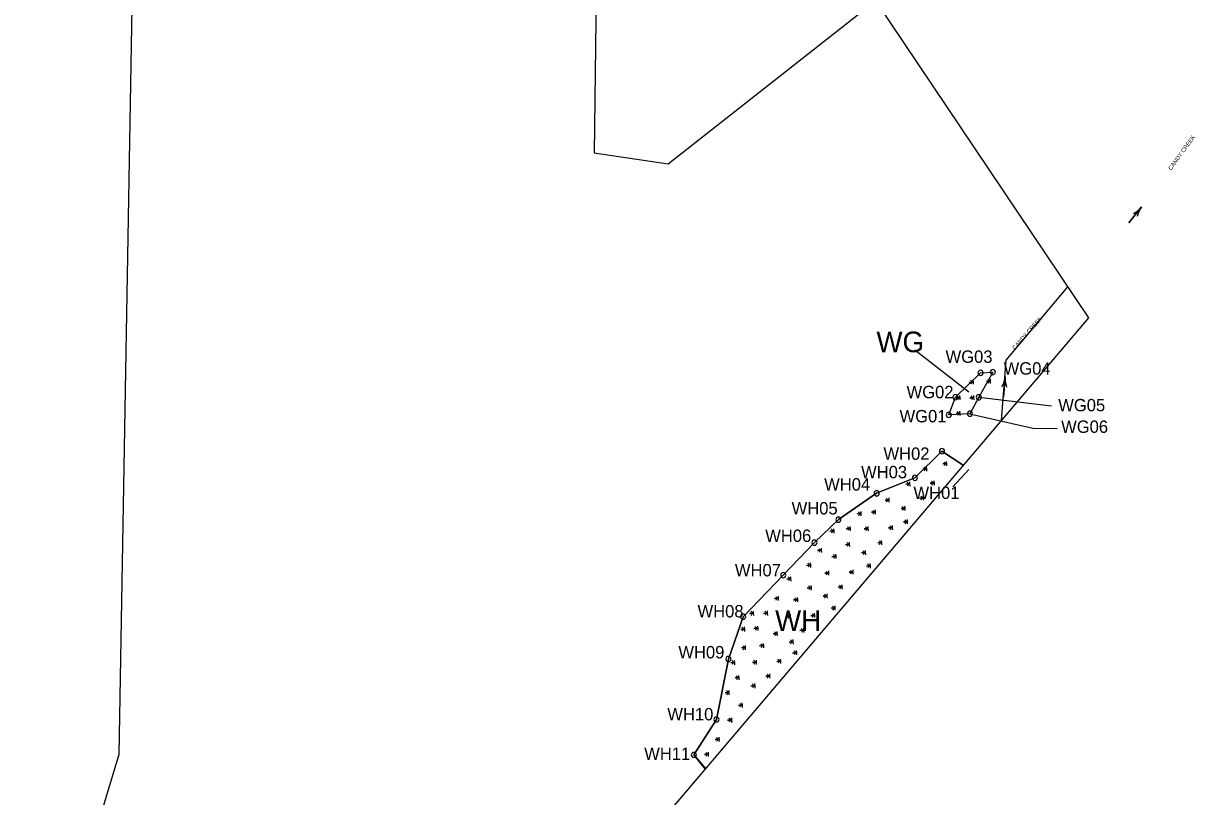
# Model space of a CAD drawing. Extents: x 1807340 to 1808565, y 913462 to 916154.
# Drawn here: x 1807430 to 1808565, y 914655 to 915405 of the extents above; entities that cross this region are included whole.
import ezdxf

# ---------------------------------------------------------------- set-up
doc = ezdxf.new("R2010")
doc.units = 0
for name, color, linetype in [('Default', 7, 'Continuous'), ('Exist Environmental Wetland Boundary', 7, 'Continuous'), ('Exist Hydro River Flow Arrow CELL', 7, 'Continuous'), ('Exist Hydro Stream or Body of Water Text', 7, 'Continuous'), ('Old_Level_60', 7, 'Continuous'), ('Old_Level_61', 7, 'Continuous'), ('Prop PHM Study Limits Alternate 1', 7, 'Continuous')]:
    doc.layers.add(name, color=color, linetype=linetype)

# ---------------------------------------------------------------- blocks, each defined once
blk = doc.blocks.new('WetlandPoint')
at = {"layer": 'Default'}
for start, end in [(0, 180), (180, 0)]:
    blk.add_arc((0, 0), 0.782, start, end, dxfattribs=at)

msp = doc.modelspace()

# ---------------------------------------------------------------- linework, layer by layer
at = {"layer": 'Default'}
msp.add_line((1808346.4, 914972.5), (1808331, 914955.6), dxfattribs=at)
msp.add_lwpolyline([(1808341.1, 914976.7), (1808320.4, 914990.3), (1808294.2, 914964.5), (1808257.1, 914949.4), (1808220, 914923.9), (1808196.8, 914901.6), (1808166.6, 914870), (1808127.7, 914829.8), (1808113.4, 914788.8), (1808101.8, 914730.1), (1808079.9, 914695.8), (1808091.1, 914682.5)], dxfattribs=at)
at = {"layer": 'Exist Environmental Wetland Boundary'}
msp.add_lwpolyline([(1808327, 915025.4), (1808333.4, 915042.7), (1808357.8, 915066.2), (1808369.7, 915066.9), (1808356.1, 915042.5), (1808347.5, 915026.6)], close=True, dxfattribs=at)
for points in [[(1808351, 915055.1), (1808350.9, 915057.2), (1808346.9, 915057), (1808350.9, 915057.2), (1808350.8, 915059.3)], [(1808367.5, 915055.9), (1808367.4, 915058), (1808363.5, 915057.8), (1808367.4, 915058), (1808367.3, 915060.2)], [(1808338, 915039.9), (1808337.9, 915042.1), (1808334, 915041.9), (1808337.9, 915042.1), (1808337.8, 915044.2)], [(1808351.5, 915039.9), (1808351.4, 915042.1), (1808347.5, 915041.9), (1808351.4, 915042.1), (1808351.3, 915044.2)], [(1808351.5, 915039.9), (1808351.4, 915042.1), (1808347.5, 915041.9), (1808351.4, 915042.1), (1808351.3, 915044.2)], [(1808338.1, 915024.7), (1808338, 915026.9), (1808334, 915026.7), (1808338, 915026.9), (1808337.8, 915029)], [(1808091, 914682.4), (1808079.9, 914695.8), (1808101.8, 914730.1), (1808113.4, 914788.8), (1808127.7, 914829.8), (1808166.6, 914870), (1808196.8, 914901.6), (1808196.8, 914901.6), (1808196.8, 914901.6), (1808196.8, 914901.6), (1808220, 914923.9), (1808257.1, 914949.4), (1808294.2, 914964.5), (1808320.4, 914990.3), (1808341.1, 914976.7)], [(1808325.2, 914976), (1808325.1, 914978.2), (1808321.1, 914977.9), (1808325.1, 914978.2), (1808324.9, 914980.3)], [(1808305.8, 914970.9), (1808305.7, 914973.1), (1808301.7, 914972.9), (1808305.7, 914973.1), (1808305.5, 914975.2)], [(1808289.5, 914956.3), (1808289.4, 914958.5), (1808285.5, 914958.2), (1808289.4, 914958.5), (1808289.3, 914960.6)], [(1808313.1, 914957.3), (1808313, 914959.4), (1808309, 914959.2), (1808313, 914959.4), (1808312.8, 914961.6)], [(1808269.3, 914940.7), (1808269.2, 914942.8), (1808265.2, 914942.6), (1808269.2, 914942.8), (1808269.1, 914945)], [(1808302.6, 914942.8), (1808302.5, 914945), (1808298.5, 914944.7), (1808302.5, 914945), (1808302.3, 914947.1)], [(1808242.2, 914927.5), (1808242.1, 914929.7), (1808238.2, 914929.5), (1808242.1, 914929.7), (1808242, 914931.8)], [(1808242.2, 914927.5), (1808242.1, 914929.7), (1808238.2, 914929.5), (1808242.1, 914929.7), (1808242, 914931.8)], [(1808256.1, 914929.1), (1808256, 914931.2), (1808252, 914931), (1808256, 914931.2), (1808255.9, 914933.4)], [(1808284.8, 914932.7), (1808284.7, 914934.8), (1808280.7, 914934.6), (1808284.7, 914934.8), (1808284.5, 914937)], [(1808287.1, 914919.8), (1808287, 914921.9), (1808283.1, 914921.7), (1808287, 914921.9), (1808286.9, 914924.1)], [(1808215.9, 914910.8), (1808215.8, 914912.9), (1808211.8, 914912.7), (1808215.8, 914912.9), (1808215.7, 914915.1)], [(1808231.7, 914913.1), (1808231.6, 914915.2), (1808227.7, 914915), (1808231.6, 914915.2), (1808231.5, 914917.3)], [(1808231.7, 914913.1), (1808231.6, 914915.2), (1808227.7, 914915), (1808231.6, 914915.2), (1808231.5, 914917.3)], [(1808249.1, 914913), (1808249, 914915.1), (1808245.1, 914914.9), (1808249, 914915.1), (1808248.9, 914917.3)], [(1808272.7, 914914), (1808272.6, 914916.1), (1808268.6, 914915.9), (1808272.6, 914916.1), (1808272.4, 914918.3)], [(1808231.1, 914897.7), (1808230.9, 914899.8), (1808227, 914899.6), (1808230.9, 914899.8), (1808230.8, 914902)], [(1808262.2, 914899.5), (1808262.1, 914901.6), (1808258.1, 914901.4), (1808262.1, 914901.6), (1808261.9, 914903.8)], [(1808203.8, 914892.1), (1808203.7, 914894.2), (1808199.7, 914894), (1808203.7, 914894.2), (1808203.6, 914896.3)], [(1808217.9, 914886.1), (1808217.7, 914888.2), (1808213.8, 914888), (1808217.7, 914888.2), (1808217.6, 914890.4)], [(1808246.5, 914889.7), (1808246.4, 914891.9), (1808242.5, 914891.6), (1808246.4, 914891.9), (1808246.3, 914894)], [(1808193.3, 914877.6), (1808193.2, 914879.7), (1808189.2, 914879.5), (1808193.2, 914879.7), (1808193.1, 914881.9)], [(1808210.9, 914870), (1808210.8, 914872.1), (1808206.8, 914871.9), (1808210.8, 914872.1), (1808210.6, 914874.3)], [(1808234.4, 914871), (1808234.3, 914873.1), (1808230.4, 914872.9), (1808234.3, 914873.1), (1808234.2, 914875.3)], [(1808251.1, 914877), (1808251, 914879.1), (1808247.1, 914878.9), (1808251, 914879.1), (1808250.9, 914881.3)], [(1808174.1, 914864.3), (1808174, 914866.4), (1808170.1, 914866.2), (1808174, 914866.4), (1808173.9, 914868.6)], [(1808193.9, 914855.6), (1808193.8, 914857.8), (1808189.8, 914857.6), (1808193.8, 914857.8), (1808193.7, 914859.9)], [(1808209.4, 914847.7), (1808209.2, 914849.8), (1808205.3, 914849.6), (1808209.2, 914849.8), (1808209.1, 914852)], [(1808223.9, 914856.5), (1808223.8, 914858.6), (1808219.9, 914858.4), (1808223.8, 914858.6), (1808223.7, 914860.8)], [(1808162, 914845.5), (1808161.9, 914847.7), (1808158, 914847.5), (1808161.9, 914847.7), (1808161.8, 914849.8)], [(1808180.7, 914844.1), (1808180.6, 914846.2), (1808176.6, 914846), (1808180.6, 914846.2), (1808180.5, 914848.3)], [(1808217, 914836.1), (1808216.9, 914838.3), (1808213, 914838.1), (1808216.9, 914838.3), (1808216.8, 914840.4)], [(1808137.9, 914831), (1808137.8, 914833.2), (1808133.9, 914832.9), (1808137.8, 914833.2), (1808137.7, 914835.3)], [(1808151.5, 914831.1), (1808151.4, 914833.2), (1808147.5, 914833), (1808151.4, 914833.2), (1808151.3, 914835.4)], [(1808173.7, 914827.9), (1808173.6, 914830.1), (1808169.6, 914829.9), (1808173.6, 914830.1), (1808173.5, 914832.2)], [(1808197.3, 914828.9), (1808197.1, 914831.1), (1808193.2, 914830.8), (1808197.1, 914831.1), (1808197, 914833.2)], [(1808129.4, 914815.6), (1808129.3, 914817.7), (1808125.3, 914817.5), (1808129.3, 914817.7), (1808129.1, 914819.9)], [(1808142.3, 914816.4), (1808142.1, 914818.6), (1808138.2, 914818.4), (1808142.1, 914818.6), (1808142, 914820.7)], [(1808186.8, 914814.5), (1808186.6, 914816.6), (1808182.7, 914816.4), (1808186.6, 914816.6), (1808186.5, 914818.7)], [(1808160.9, 914811.2), (1808160.8, 914813.4), (1808156.8, 914813.2), (1808160.8, 914813.4), (1808160.7, 914815.5)], [(1808160.9, 914811.2), (1808160.8, 914813.4), (1808156.8, 914813.2), (1808160.8, 914813.4), (1808160.7, 914815.5)], [(1808176.4, 914803.3), (1808176.3, 914805.4), (1808172.3, 914805.2), (1808176.3, 914805.4), (1808176.1, 914807.6)], [(1808176.4, 914803.3), (1808176.3, 914805.4), (1808172.3, 914805.2), (1808176.3, 914805.4), (1808176.1, 914807.6)], [(1808130.1, 914797.7), (1808130, 914799.9), (1808126.1, 914799.6), (1808130, 914799.9), (1808129.9, 914802)], [(1808147.7, 914799.7), (1808147.6, 914801.8), (1808143.6, 914801.6), (1808147.6, 914801.8), (1808147.5, 914803.9)], [(1808147.7, 914799.7), (1808147.6, 914801.8), (1808143.6, 914801.6), (1808147.6, 914801.8), (1808147.5, 914803.9)], [(1808179.7, 914792.7), (1808179.6, 914794.9), (1808175.6, 914794.6), (1808179.6, 914794.9), (1808179.4, 914797)], [(1808119.7, 914783.2), (1808119.5, 914785.4), (1808115.6, 914785.2), (1808119.5, 914785.4), (1808119.4, 914787.5)], [(1808140.7, 914783.5), (1808140.6, 914785.7), (1808136.6, 914785.5), (1808140.6, 914785.7), (1808140.5, 914787.8)], [(1808140.7, 914783.5), (1808140.6, 914785.7), (1808136.6, 914785.5), (1808140.6, 914785.7), (1808140.5, 914787.8)], [(1808164.3, 914784.5), (1808164.1, 914786.7), (1808160.2, 914786.4), (1808164.1, 914786.7), (1808164, 914788.8)], [(1808164.3, 914784.5), (1808164.1, 914786.7), (1808160.2, 914786.4), (1808164.1, 914786.7), (1808164, 914788.8)], [(1808123.8, 914768.6), (1808123.7, 914770.8), (1808119.8, 914770.5), (1808123.7, 914770.8), (1808123.6, 914772.9)], [(1808153.8, 914770.1), (1808153.6, 914772.2), (1808149.7, 914772), (1808153.6, 914772.2), (1808153.5, 914774.3)], [(1808153.8, 914770.1), (1808153.6, 914772.2), (1808149.7, 914772), (1808153.6, 914772.2), (1808153.5, 914774.3)], [(1808139.3, 914760.6), (1808139.2, 914762.8), (1808135.2, 914762.6), (1808139.2, 914762.8), (1808139, 914764.9)], [(1808114.3, 914754.1), (1808114.2, 914756.2), (1808110.3, 914756), (1808114.2, 914756.2), (1808114.1, 914758.4)], [(1808127.2, 914741.9), (1808127.1, 914744), (1808123.1, 914743.8), (1808127.1, 914744), (1808126.9, 914746.2)], [(1808116.7, 914727.4), (1808116.6, 914729.6), (1808112.6, 914729.4), (1808116.6, 914729.6), (1808116.4, 914731.7)], [(1808116.9, 914727.5), (1808116.7, 914729.6), (1808112.8, 914729.4), (1808116.7, 914729.6), (1808116.6, 914731.8)], [(1808104.7, 914708.8), (1808104.6, 914710.9), (1808100.7, 914710.7), (1808104.6, 914710.9), (1808104.5, 914713)], [(1808094.2, 914694.3), (1808094.1, 914696.4), (1808090.2, 914696.2), (1808094.1, 914696.4), (1808094, 914698.6)]]:
    msp.add_lwpolyline(points, dxfattribs=at)
for centre, radius, start, end in [((1808352.1, 915061.8), 4.81, 215.2622, 254.757), ((1808351.3, 915054.2), 3.07, 97.2751, 160.6697), ((1808368.7, 915062.7), 4.81, 215.2622, 254.757), ((1808367.8, 915055), 3.07, 97.2751, 160.6697), ((1808339.2, 915046.7), 4.81, 215.2622, 254.757), ((1808338.3, 915039), 3.07, 97.2751, 160.6697), ((1808352.7, 915046.7), 4.81, 215.2622, 254.757), ((1808352.7, 915046.7), 4.81, 215.2622, 254.757), ((1808351.8, 915039), 3.07, 97.2751, 160.6697), ((1808351.8, 915039), 3.07, 97.2751, 160.6697), ((1808339.2, 915031.5), 4.81, 215.2622, 254.757), ((1808338.3, 915023.8), 3.07, 97.2751, 160.6697), ((1808326.3, 914982.8), 4.81, 215.2622, 254.757), ((1808325.5, 914975.1), 3.07, 97.2751, 160.6697), ((1808306.9, 914977.7), 4.81, 215.2622, 254.757), ((1808306, 914970), 3.07, 97.2751, 160.6697), ((1808290.7, 914963.1), 4.81, 215.2622, 254.757), ((1808289.8, 914955.4), 3.07, 97.2751, 160.6697), ((1808314.2, 914964.1), 4.81, 215.2622, 254.757), ((1808313.3, 914956.4), 3.07, 97.2751, 160.6697), ((1808270.4, 914947.5), 4.81, 215.2622, 254.757), ((1808269.6, 914939.8), 3.07, 97.2751, 160.6697), ((1808303.7, 914949.6), 4.81, 215.2622, 254.757), ((1808302.8, 914941.9), 3.07, 97.2751, 160.6697), ((1808243.4, 914934.3), 4.81, 215.2622, 254.757), ((1808243.4, 914934.3), 4.81, 215.2622, 254.757), ((1808257.2, 914935.9), 4.81, 215.2622, 254.757), ((1808256.4, 914928.2), 3.07, 97.2751, 160.6697), ((1808285.9, 914939.5), 4.81, 215.2622, 254.757), ((1808285.1, 914931.8), 3.07, 97.2751, 160.6697), ((1808242.5, 914926.6), 3.07, 97.2751, 160.6697), ((1808242.5, 914926.6), 3.07, 97.2751, 160.6697), ((1808288.3, 914926.5), 4.81, 215.2622, 254.757), ((1808287.4, 914918.9), 3.07, 97.2751, 160.6697), ((1808217, 914917.6), 4.81, 215.2622, 254.757), ((1808216.2, 914909.9), 3.07, 97.2751, 160.6697), ((1808232.9, 914919.8), 4.81, 215.2622, 254.757), ((1808232.9, 914919.8), 4.81, 215.2622, 254.757), ((1808232, 914912.2), 3.07, 97.2751, 160.6697), ((1808232, 914912.2), 3.07, 97.2751, 160.6697), ((1808250.3, 914919.8), 4.81, 215.2622, 254.757), ((1808249.4, 914912.1), 3.07, 97.2751, 160.6697), ((1808273.8, 914920.7), 4.81, 215.2622, 254.757), ((1808272.9, 914913.1), 3.07, 97.2751, 160.6697), ((1808232.2, 914904.5), 4.81, 215.2622, 254.757), ((1808231.3, 914896.8), 3.07, 97.2751, 160.6697), ((1808263.3, 914906.3), 4.81, 215.2622, 254.757), ((1808262.4, 914898.6), 3.07, 97.2751, 160.6697), ((1808204.9, 914898.8), 4.81, 215.2622, 254.757), ((1808204.1, 914891.2), 3.07, 97.2751, 160.6697), ((1808219, 914892.9), 4.81, 215.2622, 254.757), ((1808218.1, 914885.2), 3.07, 97.2751, 160.6697), ((1808247.7, 914896.5), 4.81, 215.2622, 254.757), ((1808246.8, 914888.8), 3.07, 97.2751, 160.6697), ((1808194.4, 914884.4), 4.81, 215.2622, 254.757), ((1808193.6, 914876.7), 3.07, 97.2751, 160.6697), ((1808235.6, 914877.7), 4.81, 215.2622, 254.757), ((1808252.3, 914883.8), 4.81, 215.2622, 254.757), ((1808251.4, 914876.1), 3.07, 97.2751, 160.6697), ((1808175.3, 914871.1), 4.81, 215.2622, 254.757), ((1808174.4, 914863.4), 3.07, 97.2751, 160.6697), ((1808212, 914876.8), 4.81, 215.2622, 254.757), ((1808211.1, 914869.1), 3.07, 97.2751, 160.6697), ((1808234.7, 914870.1), 3.07, 97.2751, 160.6697), ((1808195, 914862.4), 4.81, 215.2622, 254.757), ((1808194.2, 914854.7), 3.07, 97.2751, 160.6697), ((1808210.5, 914854.4), 4.81, 215.2622, 254.757), ((1808225.1, 914863.3), 4.81, 215.2622, 254.757), ((1808224.2, 914855.6), 3.07, 97.2751, 160.6697), ((1808163.2, 914852.3), 4.81, 215.2622, 254.757), ((1808162.3, 914844.6), 3.07, 97.2751, 160.6697), ((1808181.8, 914850.8), 4.81, 215.2622, 254.757), ((1808181, 914843.1), 3.07, 97.2751, 160.6697), ((1808209.6, 914846.8), 3.07, 97.2751, 160.6697), ((1808139.1, 914837.8), 4.81, 215.2622, 254.757), ((1808138.2, 914830.1), 3.07, 97.2751, 160.6697), ((1808152.7, 914837.8), 4.81, 215.2622, 254.757), ((1808151.8, 914830.2), 3.07, 97.2751, 160.6697), ((1808174.8, 914834.7), 4.81, 215.2622, 254.757), ((1808174, 914827), 3.07, 97.2751, 160.6697), ((1808198.4, 914835.7), 4.81, 215.2622, 254.757), ((1808197.5, 914828), 3.07, 97.2751, 160.6697), ((1808218.2, 914842.9), 4.81, 215.2622, 254.757), ((1808217.3, 914835.2), 3.07, 97.2751, 160.6697), ((1808130.5, 914822.4), 4.81, 215.2622, 254.757), ((1808129.6, 914814.7), 3.07, 97.2751, 160.6697), ((1808143.4, 914823.2), 4.81, 215.2622, 254.757), ((1808142.5, 914815.5), 3.07, 97.2751, 160.6697), ((1808187.9, 914821.2), 4.81, 215.2622, 254.757), ((1808162, 914818), 4.81, 215.2622, 254.757), ((1808162, 914818), 4.81, 215.2622, 254.757), ((1808161.2, 914810.3), 3.07, 97.2751, 160.6697), ((1808161.2, 914810.3), 3.07, 97.2751, 160.6697), ((1808177.5, 914810), 4.81, 215.2622, 254.757), ((1808177.5, 914810), 4.81, 215.2622, 254.757), ((1808187, 914813.5), 3.07, 97.2751, 160.6697), ((1808131.3, 914804.5), 4.81, 215.2622, 254.757), ((1808130.4, 914796.8), 3.07, 97.2751, 160.6697), ((1808148.8, 914806.4), 4.81, 215.2622, 254.757), ((1808148.8, 914806.4), 4.81, 215.2622, 254.757), ((1808148, 914798.7), 3.07, 97.2751, 160.6697), ((1808148, 914798.7), 3.07, 97.2751, 160.6697), ((1808176.6, 914802.4), 3.07, 97.2751, 160.6697), ((1808176.6, 914802.4), 3.07, 97.2751, 160.6697), ((1808180.8, 914799.5), 4.81, 215.2622, 254.757), ((1808179.9, 914791.8), 3.07, 97.2751, 160.6697), ((1808120.8, 914790), 4.81, 215.2622, 254.757), ((1808119.9, 914782.3), 3.07, 97.2751, 160.6697), ((1808141.8, 914790.3), 4.81, 215.2622, 254.757), ((1808141.8, 914790.3), 4.81, 215.2622, 254.757), ((1808141, 914782.6), 3.07, 97.2751, 160.6697), ((1808141, 914782.6), 3.07, 97.2751, 160.6697), ((1808165.4, 914791.3), 4.81, 215.2622, 254.757), ((1808165.4, 914791.3), 4.81, 215.2622, 254.757), ((1808164.5, 914783.6), 3.07, 97.2751, 160.6697), ((1808164.5, 914783.6), 3.07, 97.2751, 160.6697), ((1808125, 914775.4), 4.81, 215.2622, 254.757), ((1808154.9, 914776.8), 4.81, 215.2622, 254.757), ((1808154.9, 914776.8), 4.81, 215.2622, 254.757), ((1808154, 914769.1), 3.07, 97.2751, 160.6697), ((1808154, 914769.1), 3.07, 97.2751, 160.6697), ((1808124.1, 914767.7), 3.07, 97.2751, 160.6697), ((1808140.4, 914767.4), 4.81, 215.2622, 254.757), ((1808139.6, 914759.7), 3.07, 97.2751, 160.6697), ((1808115.5, 914760.9), 4.81, 215.2622, 254.757), ((1808114.6, 914753.2), 3.07, 97.2751, 160.6697), ((1808128.3, 914748.7), 4.81, 215.2622, 254.757), ((1808127.4, 914741), 3.07, 97.2751, 160.6697), ((1808117.8, 914734.2), 4.81, 215.2622, 254.757), ((1808117, 914726.5), 3.07, 97.2751, 160.6697), ((1808118, 914734.3), 4.81, 215.2622, 254.757), ((1808117.1, 914726.6), 3.07, 97.2751, 160.6697), ((1808105.9, 914715.5), 4.81, 215.2622, 254.757), ((1808105, 914707.8), 3.07, 97.2751, 160.6697), ((1808095.4, 914701.1), 4.81, 215.2622, 254.757), ((1808094.5, 914693.4), 3.07, 97.2751, 160.6697)]:
    msp.add_arc(centre, radius, start, end, dxfattribs=at)
at = {"layer": 'Exist Hydro River Flow Arrow CELL'}
for p, q in [((1808507.7, 915219.3), (1808507.7, 915219.3)), ((1808380.8, 915052.5), (1808380.8, 915052.5))]:
    msp.add_line(p, q, dxfattribs=at)
for points in [[(1808505.9, 915220.7), (1808507.7, 915221.7), (1808509.5, 915222.9), (1808511.1, 915224.2), (1808512.6, 915225.6), (1808513.9, 915227.2), (1808501.5, 915211.5), (1808513.9, 915227.2), (1808512.7, 915225.5), (1808511.7, 915223.7), (1808510.8, 915221.8), (1808510.1, 915219.9), (1808509.5, 915217.9)], [(1808378.5, 915052.7), (1808379.5, 915054.5), (1808380.3, 915056.5), (1808380.9, 915058.5), (1808381.4, 915060.5), (1808381.6, 915062.5), (1808380, 915042.6), (1808381.6, 915062.5), (1808381.5, 915060.5), (1808381.7, 915058.4), (1808382, 915056.3), (1808382.5, 915054.3), (1808383.1, 915052.4)]]:
    msp.add_lwpolyline(points, dxfattribs=at)
at = {"layer": 'Old_Level_60'}
for points in [[(1808346.6, 915047.4), (1808294.2, 915088.1)], [(1808356.1, 915042.5), (1808426.5, 915034.2)], [(1808347.5, 915026.6), (1808408.6, 915012.6), (1808431.9, 915012.1)]]:
    msp.add_lwpolyline(points, dxfattribs=at)
at = {"layer": 'Old_Level_61'}
msp.add_lwpolyline([(1808378, 915020.1), (1808382.5, 915078.6), (1808442.4, 915149.6)], dxfattribs=at)
at = {"layer": 'Prop PHM Study Limits Alternate 1'}
msp.add_lwpolyline([(1807430.1, 914388.9), (1807519.9, 914687), (1807522.8, 914696.1), (1807538, 915569.7), (1807588.4, 915634.3), (1807588.3, 915636.5), (1807645.3, 915707.7), (1807658.1, 915723.7), (1807648.7, 915775.6), (1807707.5, 915787), (1807994.3, 916154.4), (1807983.4, 915279.5), (1808055, 915268.9), (1808255.9, 915426.9), (1808462.5, 915119.6), (1807995.2, 914569.7)], dxfattribs=at)

# ---------------------------------------------------------------- block references
at = {"layer": 'Default', "xscale": 3.198862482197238, "yscale": 3.198862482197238}
for p in [(1808320.4, 914990.3), (1808294.2, 914964.5), (1808257.1, 914949.4), (1808220, 914923.9), (1808196.8, 914901.6), (1808166.6, 914870), (1808127.7, 914829.8), (1808113.4, 914788.8), (1808101.8, 914730.1), (1808079.9, 914695.8)]:
    msp.add_blockref('WetlandPoint', p, dxfattribs=at)
at = {"layer": 'Old_Level_60', "xscale": 3.198862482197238, "yscale": 3.198862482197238}
for p in [(1808357.8, 915066.2), (1808369.7, 915066.9), (1808333.4, 915042.7), (1808356.1, 915042.5), (1808327, 915025.4), (1808347.5, 915026.6), (1808320.4, 914990.3), (1808294.2, 914964.5), (1808257.1, 914949.4), (1808220, 914923.9), (1808196.8, 914901.6), (1808166.6, 914870), (1808127.7, 914829.8), (1808113.4, 914788.8), (1808101.8, 914730.1), (1808079.9, 914695.8)]:
    msp.add_blockref('WetlandPoint', p, dxfattribs=at)

# ---------------------------------------------------------------- texts
at = {"layer": 'Default'}
for s, p in [('WH02', (1808263.7, 914981.9)), ('WH03', (1808242, 914964)), ('WH04', (1808206.2, 914952.1)), ('WH01', (1808292.8, 914943.9)), ('WH05', (1808174.7, 914928.9)), ('WH06', (1808149.1, 914902.3)), ('WH07', (1808119.7, 914868.9)), ('WH08', (1808083.5, 914829.1)), ('WH09', (1808064.9, 914789.4)), ('WH10', (1808054.2, 914729.3)), ('WH11', (1808031.8, 914691))]:
    msp.add_text(s, height=12, dxfattribs=at).set_placement(p)
at = {"layer": 'Exist Hydro Stream or Body of Water Text'}
for rotation, p in [(54.0436, (1808542.6, 915262.3)), (48.3312, (1808391.1, 915088.4))]:
    msp.add_text('CANDY CREEK', height=4, rotation=rotation, dxfattribs=at).set_placement(p)
at = {"layer": 'Old_Level_60'}
for s, height, p in [('WG', 20, (1808256.9, 915086.2)), ('WG03', 12, (1808323.9, 915075.9)), ('WG04', 12, (1808380.2, 915064.5)), ('WG02', 12, (1808286.1, 915041.6)), ('WG05', 12, (1808433.1, 915028.9)), ('WG01', 12, (1808279.3, 915018.2)), ('WG06', 12, (1808435.9, 915008)), ('WH02', 12, (1808263.7, 914981.9)), ('WH03', 12, (1808242, 914964)), ('WH04', 12, (1808206.2, 914952.1)), ('WH05', 12, (1808174.7, 914928.9)), ('WH06', 12, (1808149.1, 914902.3)), ('WH07', 12, (1808119.7, 914868.9)), ('WH08', 12, (1808083.5, 914829.1)), ('WH', 20, (1808158.7, 914816)), ('WH09', 12, (1808064.9, 914789.4)), ('WH10', 12, (1808054.2, 914729.3)), ('WH11', 12, (1808031.8, 914691))]:
    msp.add_text(s, height=height, dxfattribs=at).set_placement(p)

doc.saveas('drawing.dxf')
